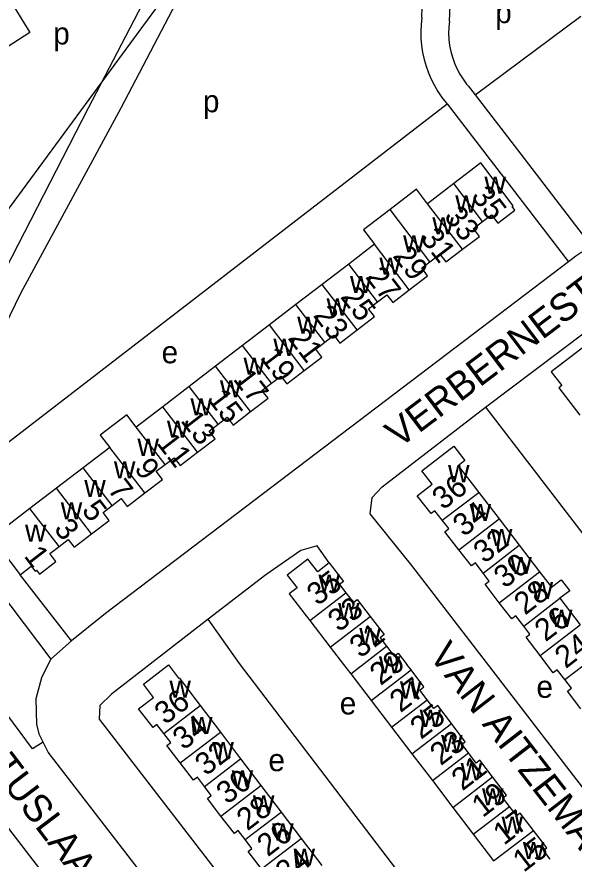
# Model space of a CAD drawing. Extents: x 158848 to 160613, y 385889 to 387762.
# Drawn here: x 159871.5 to 159971.7, y 386965 to 387116.4 of the extents above; entities that cross this region are included whole.
import ezdxf

# ---------------------------------------------------------------- set-up
doc = ezdxf.new("R2010")
doc.units = 0
for name, color, linetype in [('BLT_Basislijn', 7, 'Continuous'), ('BLT_Bebouwing', 7, 'Continuous'), ('BLT_Centroide', 7, 'Continuous'), ('BLT_Hoogspanningsmast_en_leidingen', 7, 'Continuous'), ('BLT_Huisnummer', 7, 'Continuous'), ('BLT_Huisnummer_ tussenligend', 7, 'Continuous'), ('BLT_Onderverdeling_panden', 7, 'Continuous'), ('BLT_Straatnaam', 7, 'Continuous')]:
    doc.layers.add(name, color=color, linetype=linetype)

msp = doc.modelspace()

# ---------------------------------------------------------------- linework, layer by layer
at = {"layer": 'BLT_Basislijn'}
for p, q in [((159944.31, 387116.32), (159945.27, 387143.28)), ((159949.27, 387115.66), (159950.38, 387138.71)), ((159953.88, 387102.42), (159972.89, 387116.56)), ((159952.64, 387104.03), (159953.88, 387102.42)), ((159953.88, 387102.42), (159962.7, 387090.95)), ((159860.03, 387032.3), (159948.85, 387100.76)), ((159948.74, 387100.89), (159948.85, 387100.76)), ((159948.85, 387100.76), (159970.69, 387072.37)), ((159962.7, 387090.95), (159974.73, 387075.31)), ((159955.74, 387046.28), (160003.04, 386984.63)), ((159851.06, 387036.1), (159877.63, 387000.96)), ((159881.34, 387004.23), (159872.1, 387016.13)), ((159877.63, 387000.96), (159881.34, 387004.23)), ((159849.79, 386996.78), (159888.25, 386946.8))]:
    msp.add_line(p, q, dxfattribs=at)
for points in [[(159910.62, 387195.56), (159926.67, 387162.23), (159927.14, 387160.7), (159900.93, 387130.86), (159900.07, 387130.23), (159884.36, 387100), (159859.01, 387050.73), (159856.32, 387045.74), (159852.75, 387041.99)], [(159945.27, 387143.28), (159931.76, 387155.39), (159930.71, 387156.05), (159923.76, 387148.68), (159904.06, 387126.47), (159890.19, 387100), (159872.2, 387066.71), (159869.35, 387060.89), (159856.52, 387037.21)], [(159868.37, 387122.56), (159873.87, 387113.59), (159852.89, 387100.09)], [(159944.31, 387116.32), (159944.18, 387115.06), (159944.13, 387113.8), (159944.17, 387112.53), (159944.28, 387111.27), (159944.47, 387110.02), (159944.74, 387108.78), (159945.09, 387107.57), (159945.51, 387106.37), (159946.01, 387105.21), (159946.58, 387104.08), (159947.22, 387102.99), (159947.93, 387101.94), (159948.74, 387100.89)], [(159949.27, 387115.66), (159949.16, 387114.57), (159949.13, 387113.47), (159949.19, 387112.38), (159949.32, 387111.29), (159949.54, 387110.21), (159949.83, 387109.16), (159950.2, 387108.12), (159950.64, 387107.12), (159951.15, 387106.15), (159951.73, 387105.23), (159952.38, 387104.34), (159952.64, 387104.03)], [(159973.07, 387074.13), (159972.02, 387073.38), (159970.69, 387072.37)], [(159970.69, 387072.37), (159887.47, 387009.18), (159881.34, 387004.23)], [(159955.74, 387046.28), (159973.72, 387059.77), (159976.37, 387060.31), (159979.04, 387057.18)], [(159980.79, 386968.05), (159942.54, 387017.82), (159935.06, 387027.05), (159935.38, 387030.01), (159937.2, 387031.92), (159955.74, 387046.28)], [(159927.68, 387018.25), (159925.48, 387021.34), (159922.59, 387020.49), (159916.28, 387016.13), (159905.89, 387008.12)], [(159905.89, 387008.12), (159888.53, 386994.63), (159886.45, 386992.62), (159886.3, 386990.14), (159932.39, 386930.43)], [(159952.83, 386946.07), (159952.54, 386946.44), (159911.56, 387000.19), (159905.89, 387008.12)], [(159876.25, 386986.01), (159874.33, 386984.83), (159859.57, 387004.69)], [(159876.25, 386986.01), (159875.57, 386987.34), (159875.13, 386989.22), (159874.99, 386993.89), (159876.01, 386997.64), (159877.63, 387000.96)], [(159888.25, 386946.8), (159893.86, 386951.01), (159895.61, 386953.26), (159896.32, 386955.03), (159896.41, 386958.32), (159895.77, 386960.07), (159877.16, 386984.25), (159876.25, 386986.01)]]:
    msp.add_lwpolyline(points, dxfattribs=at)
at = {"layer": 'BLT_Bebouwing'}
for p, q in [((159950.07, 387086.45), (159945.36, 387082.83)), ((159935.83, 387075.53), (159931.18, 387071.97)), ((159931.18, 387071.97), (159926.43, 387068.33)), ((159926.43, 387068.33), (159921.7, 387064.7)), ((159921.7, 387064.7), (159916.91, 387061.03)), ((159916.91, 387061.03), (159912.08, 387057.32)), ((159912.08, 387057.32), (159907.26, 387053.63)), ((159907.26, 387053.63), (159902.51, 387049.99)), ((159902.51, 387049.99), (159897.74, 387046.34)), ((159897.74, 387046.34), (159892.97, 387042.68)), ((159888.21, 387039.03), (159883.42, 387035.36)), ((159883.42, 387035.36), (159878.65, 387031.71)), ((159878.65, 387031.71), (159873.87, 387028.04)), ((159954.57, 387030.91), (159958.21, 387026.16)), ((159873.87, 387028.04), (159867.1, 387022.85)), ((159958.21, 387026.16), (159961.84, 387021.42)), ((159961.84, 387021.42), (159965.5, 387016.65)), ((159969.15, 387011.89), (159972.8, 387007.12)), ((159924.17, 387007.92), (159927.86, 387003.13)), ((159927.86, 387003.13), (159930.27, 387000)), ((159966.81, 387000), (159965.59, 387001.59)), ((159930.27, 387000), (159931.54, 386998.33)), ((159942.38, 386999.02), (159941.63, 387000)), ((159931.54, 386998.33), (159935.21, 386993.53)), ((159904.5, 386992.61), (159908.11, 386987.84)), ((159935.21, 386993.53), (159938.88, 386988.72)), ((159908.11, 386987.84), (159911.73, 386983.06)), ((159938.88, 386988.72), (159942.55, 386983.92)), ((159911.73, 386983.06), (159915.38, 386978.25)), ((159942.55, 386983.92), (159946.21, 386979.11)), ((159946.21, 386979.11), (159949.88, 386974.31)), ((159915.38, 386978.25), (159919.01, 386973.47)), ((159949.88, 386974.31), (159953.55, 386969.5)), ((159919.01, 386973.47), (159922.62, 386968.7)), ((159953.55, 386969.5), (159957.22, 386964.7)), ((159922.62, 386968.7), (159926.32, 386963.83))]:
    msp.add_line(p, q, dxfattribs=at)
for points in [[(159955.22, 387079.61), (159956.85, 387080.83), (159957.97, 387079.34), (159961.07, 387081.68), (159960.57, 387082.34), (159960.75, 387082.47), (159954.95, 387090.19), (159950.07, 387086.45)], [(159945.36, 387082.83), (159943.38, 387085.43), (159938.61, 387081.8)], [(159938.61, 387081.8), (159933.83, 387078.15), (159935.83, 387075.53)], [(159951.66, 387074.66), (159954.68, 387076.93), (159953.59, 387078.38), (159955.22, 387079.61)], [(159945.76, 387072.41), (159947.56, 387073.79), (159948.63, 387072.39), (159951.66, 387074.66)], [(159942.07, 387067.36), (159945.37, 387069.89), (159944.3, 387071.29), (159945.76, 387072.41)], [(159936.37, 387065.21), (159938.02, 387066.47), (159939.09, 387065.07), (159942.07, 387067.36)], [(159932.7, 387060.16), (159935.81, 387062.54), (159934.73, 387063.94), (159936.37, 387065.21)], [(159926.9, 387057.92), (159928.53, 387059.17), (159929.6, 387057.78), (159932.7, 387060.16)], [(159923.2, 387052.85), (159926.35, 387055.27), (159925.27, 387056.67), (159926.9, 387057.92)], [(159979.04, 387057.18), (159976.47, 387055.2), (159974.43, 387057.85), (159967.6, 387052.61), (159969.48, 387050.15), (159968.95, 387049.73), (159972.74, 387044.83)], [(159917.27, 387050.56), (159918.95, 387051.85), (159920.04, 387050.43), (159923.2, 387052.85)], [(159913.54, 387045.45), (159916.68, 387047.85), (159915.59, 387049.27), (159917.27, 387050.56)], [(159907.72, 387043.2), (159909.34, 387044.44), (159910.41, 387043.04), (159913.54, 387045.45)], [(159892.97, 387042.68), (159891.28, 387044.9), (159886.52, 387041.25), (159888.21, 387039.03)], [(159904.02, 387038.17), (159907.17, 387040.59), (159906.11, 387041.96), (159907.72, 387043.2)], [(159947.99, 387025.92), (159946.66, 387027.63), (159946.01, 387027.11), (159943.51, 387030.32), (159946.19, 387032.41), (159944.35, 387034.78), (159950.06, 387039.22), (159952.07, 387036.65), (159950.87, 387035.72), (159953.77, 387031.94), (159954.57, 387030.91)], [(159898.18, 387035.94), (159899.78, 387037.17), (159900.87, 387035.75), (159904.02, 387038.17)], [(159894.52, 387030.85), (159897.68, 387033.28), (159896.58, 387034.72), (159898.18, 387035.94)], [(159888.64, 387028.57), (159890.27, 387029.83), (159891.36, 387028.42), (159894.52, 387030.85)], [(159884.96, 387023.49), (159888.1, 387025.9), (159887.01, 387027.32), (159888.64, 387028.57)], [(159950.95, 387020.63), (159948.44, 387023.86), (159949.16, 387024.42), (159947.99, 387025.92)], [(159867.1, 387022.85), (159867, 387022.77), (159872.1, 387016.13)], [(159879.12, 387021.21), (159880.76, 387022.47), (159881.82, 387021.08), (159884.96, 387023.49)], [(159872.1, 387016.13), (159874.12, 387017.68), (159874.81, 387016.79), (159875.04, 387016.96), (159875.59, 387016.25), (159878.56, 387018.53), (159877.48, 387019.95), (159879.12, 387021.21)], [(159955.34, 387016.43), (159953.94, 387018.25), (159953.23, 387017.71), (159950.95, 387020.63)], [(159927.68, 387018.25), (159925.62, 387016.67), (159923.85, 387018.92), (159920.13, 387016.03), (159921.9, 387013.8), (159920.48, 387012.71), (159923.53, 387008.74), (159924.17, 387007.92)], [(159927.68, 387018.25), (159930.26, 387014.9), (159929.53, 387014.35), (159930.66, 387012.88)], [(159958.25, 387011.09), (159955.7, 387014.42), (159956.44, 387014.99), (159955.34, 387016.43)], [(159965.5, 387016.65), (159967.63, 387013.89), (159969.39, 387015.23), (159970.91, 387013.24), (159969.15, 387011.89)], [(159930.66, 387012.88), (159932.01, 387011.13), (159932.7, 387011.67), (159935.04, 387008.62)], [(159962.64, 387006.89), (159961.22, 387008.74), (159960.49, 387008.18), (159958.25, 387011.09)], [(159935.04, 387008.62), (159937.56, 387005.36), (159936.83, 387004.8), (159938, 387003.27)], [(159965.59, 387001.59), (159963.05, 387004.91), (159963.75, 387005.44), (159962.64, 387006.89)], [(159938, 387003.27), (159939.35, 387001.52), (159940.05, 387002.06), (159941.63, 387000)], [(159897.94, 386987.58), (159896.69, 386989.2), (159896, 386988.67), (159893.42, 386992.04), (159896.08, 386994.08), (159894.26, 386996.46), (159898.76, 386999.91), (159900.58, 386997.53), (159900.7, 386997.62), (159903.72, 386993.63), (159904.5, 386992.61)], [(159970, 386997.28), (159968.65, 386999.03), (159967.95, 386998.49), (159966.81, 387000)], [(159945.3, 386993.64), (159943.95, 386995.4), (159944.7, 386995.97), (159942.38, 386999.02)], [(159972.92, 386992.05), (159970.52, 386995.17), (159971.21, 386995.71), (159970, 386997.28)], [(159949.67, 386989.36), (159947.18, 386992.65), (159946.48, 386992.11), (159945.3, 386993.64)], [(159952.71, 386984.09), (159951.52, 386985.65), (159952.13, 386986.11), (159949.67, 386989.36)], [(159900.9, 386982.31), (159898.51, 386985.43), (159899.18, 386985.95), (159897.94, 386987.58)], [(159957.05, 386979.79), (159954.76, 386982.77), (159954.11, 386982.27), (159952.71, 386984.09)], [(159905.23, 386978.08), (159903.98, 386979.71), (159903.3, 386979.19), (159900.9, 386982.31)], [(159960.08, 386974.49), (159958.9, 386976.03), (159959.54, 386976.52), (159957.05, 386979.79)], [(159908.2, 386972.74), (159905.77, 386975.9), (159906.48, 386976.44), (159905.23, 386978.08)], [(159964.38, 386970.17), (159962.02, 386973.25), (159961.39, 386972.77), (159960.08, 386974.49)], [(159912.54, 386968.52), (159911.31, 386970.12), (159910.62, 386969.59), (159908.2, 386972.74)], [(159967.37, 386964.97), (159966.17, 386966.53), (159966.8, 386967.01), (159964.38, 386970.17)], [(159915.49, 386963.23), (159913.08, 386966.38), (159913.77, 386966.91), (159912.54, 386968.52)]]:
    msp.add_lwpolyline(points, dxfattribs=at)
at = {"layer": 'BLT_Hoogspanningsmast_en_leidingen'}
msp.add_line((159845.08, 387048.01), (159951.04, 387192.01), dxfattribs=at)
at = {"layer": 'BLT_Onderverdeling_panden'}
for p, q in [((159955.22, 387079.61), (159950.07, 387086.45)), ((159945.76, 387072.41), (159938.61, 387081.8)), ((159951.66, 387074.66), (159945.36, 387082.83)), ((159942.07, 387067.36), (159935.83, 387075.53)), ((159936.37, 387065.21), (159931.18, 387071.97)), ((159932.7, 387060.16), (159926.43, 387068.33)), ((159926.9, 387057.92), (159921.7, 387064.7)), ((159923.2, 387052.85), (159916.91, 387061.03)), ((159917.27, 387050.56), (159912.08, 387057.32)), ((159913.54, 387045.45), (159907.26, 387053.63)), ((159907.72, 387043.2), (159902.51, 387049.99)), ((159904.02, 387038.17), (159897.74, 387046.34)), ((159898.18, 387035.94), (159892.97, 387042.68)), ((159894.52, 387030.85), (159888.21, 387039.03)), ((159888.64, 387028.57), (159883.42, 387035.36)), ((159884.96, 387023.49), (159878.65, 387031.71)), ((159947.99, 387025.92), (159954.57, 387030.91)), ((159879.12, 387021.21), (159873.87, 387028.04)), ((159950.95, 387020.63), (159958.21, 387026.16)), ((159955.34, 387016.43), (159961.84, 387021.42)), ((159958.25, 387011.09), (159965.5, 387016.65)), ((159924.17, 387007.92), (159930.66, 387012.88)), ((159962.64, 387006.89), (159969.15, 387011.89)), ((159927.86, 387003.13), (159935.04, 387008.62)), ((159965.59, 387001.59), (159972.8, 387007.12)), ((159970, 386997.28), (159979.1, 387004.25)), ((159931.54, 386998.33), (159938, 387003.27)), ((159935.21, 386993.53), (159942.38, 386999.02)), ((159938.88, 386988.72), (159945.3, 386993.64)), ((159897.94, 386987.58), (159904.5, 386992.61)), ((159942.55, 386983.92), (159949.67, 386989.36)), ((159900.9, 386982.31), (159908.11, 386987.84)), ((159905.23, 386978.08), (159911.73, 386983.06)), ((159946.21, 386979.11), (159952.71, 386984.09)), ((159949.88, 386974.31), (159957.05, 386979.79)), ((159908.2, 386972.74), (159915.38, 386978.25)), ((159953.55, 386969.5), (159960.08, 386974.49)), ((159912.54, 386968.52), (159919.01, 386973.47)), ((159957.22, 386964.7), (159964.38, 386970.17)), ((159915.49, 386963.23), (159922.62, 386968.7))]:
    msp.add_line(p, q, dxfattribs=at)

# ---------------------------------------------------------------- texts
at = {"layer": 'BLT_Centroide'}
for s, p in [('p', (159957.51, 387115.29)), ('p', (159878.06, 387111.45)), ('p', (159904.97, 387099.27)), ('w', (159955.58, 387084.62)), ('w', (159950.34, 387081.25)), ('w', (159946.2, 387077.34)), ('w', (159940.95, 387074.09)), ('w', (159936.7, 387070.08)), ('w', (159931.41, 387066.77)), ('w', (159927.2, 387062.73)), ('w', (159921.91, 387059.48)), ('e', (159897.54, 387054.14)), ('w', (159917.64, 387055.47)), ('w', (159912.27, 387052.09)), ('w', (159908.03, 387048.03)), ('w', (159902.73, 387044.77)), ('w', (159898.5, 387040.77)), ('w', (159893.2, 387037.5)), ('w', (159888.97, 387033.44)), ('w', (159949.03, 387032.77)), ('w', (159883.64, 387030.12)), ('w', (159879.42, 387026.08)), ('w', (159952.91, 387025.78)), ('w', (159872.98, 387022.09)), ('w', (159956.74, 387021.28)), ('w', (159960.23, 387016.25)), ('w', (159925.73, 387013.09)), ('w', (159964.07, 387011.78)), ('w', (159929.26, 387008)), ('w', (159967.52, 387006.75)), ('w', (159933.08, 387003.47)), ('w', (159936.6, 386998.41)), ('w', (159898.95, 386994.02)), ('w', (159940.39, 386993.88)), ('e', (159964.92, 386994)), ('e', (159929.57, 386991.02)), ('w', (159902.83, 386987.47)), ('w', (159943.93, 386988.78)), ('w', (159906.67, 386982.97)), ('w', (159947.78, 386984.25)), ('e', (159916.74, 386980.82)), ('w', (159951.3, 386979.19)), ('w', (159910.14, 386977.91)), ('w', (159955.14, 386974.66)), ('w', (159913.96, 386973.38)), ('w', (159958.65, 386969.59)), ('w', (159917.42, 386968.34)), ('w', (159962.48, 386965.03)), ('w', (159921.27, 386963.81))]:
    msp.add_text(s, height=4, dxfattribs=at).set_placement(p)
at = {"layer": 'BLT_Huisnummer'}
for s, rotation, p in [('35', 307.529, (159953.06, 387084.15)), ('29', 307.529, (159938.97, 387073.41)), ('25', 307.529, (159929.55, 387066.06)), ('21', 307.529, (159920.1, 387058.65)), ('17', 307.529, (159910.27, 387051.28)), ('13', 307.529, (159900.83, 387043.82)), ('9', 307.529, (159892.49, 387035.2)), ('36', 37.6238, (159948.14, 387027.65)), ('5', 307.529, (159883.04, 387027.68)), ('1', 307.529, (159872.68, 387019.47)), ('30', 37.6238, (159959.22, 387013.54)), ('35', 37.4113, (159925.59, 387010.43)), ('26', 37.6238, (159966.55, 387003.95)), ('29', 37.4113, (159936.91, 386996.09)), ('36', 37.4841, (159898.21, 386989.05)), ('25', 37.4113, (159944.17, 386986.42)), ('21', 37.4113, (159951.61, 386977.16)), ('30', 37.4841, (159909.33, 386974.71)), ('17', 37.4113, (159959.08, 386967.38)), ('26', 37.4841, (159916.64, 386965.32))]:
    msp.add_text(s, height=4, rotation=rotation, dxfattribs=at).set_placement(p)
at = {"layer": 'BLT_Huisnummer_ tussenligend'}
for s, rotation, p in [('33', 307.529, (159948.17, 387080.51)), ('31', 307.529, (159943.92, 387076.6)), ('27', 307.529, (159934.06, 387069.62)), ('23', 307.529, (159924.67, 387062.72)), ('19', 307.529, (159915.12, 387055.14)), ('15', 307.529, (159905.67, 387047.69)), ('11', 307.529, (159896.5, 387039.79)), ('7', 307.529, (159887.71, 387031.4)), ('34', 37.6238, (159951.86, 387022.83)), ('3', 307.529, (159878.05, 387024.34)), ('32', 37.6238, (159955.55, 387018.03)), ('28', 37.6238, (159962.87, 387008.75)), ('33', 37.4113, (159929.39, 387005.7)), ('31', 37.4113, (159933.27, 387001.01)), ('24', 37.6238, (159970.18, 386999.14)), ('27', 37.4113, (159940.48, 386991.21)), ('34', 37.4841, (159901.49, 386984.47)), ('23', 37.4113, (159947.73, 386981.69)), ('32', 37.4841, (159905.5, 386979.84)), ('19', 37.4113, (159955.25, 386972.35)), ('28', 37.4841, (159912.97, 386969.97)), ('15', 37.4337, (159962.62, 386962.51)), ('24', 37.4841, (159919.97, 386960.51))]:
    msp.add_text(s, height=4, rotation=rotation, dxfattribs=at).set_placement(p)
at = {"layer": 'BLT_Straatnaam'}
for s, rotation, p in [('VERBERNESTRAAT', 37.1354, (159940.21, 387038.76)), ('VAN AITZEMASTRAAT', 307.8301, (159945.46, 387001.57)), ('TACITUSLAAN', 307.2564, (159857.31, 386993.69))]:
    msp.add_text(s, height=5, rotation=rotation, dxfattribs=at).set_placement(p)

doc.saveas('drawing.dxf')
